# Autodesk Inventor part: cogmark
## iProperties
Author: Neil
Shininess: 42.0
Angle Display Precision: 2
Document Length Units: 11272
Document Angle Units: 11286
Document Time Units: 11279
Document Mass Units: 11290
Document Length Units Precision: 3
Document Angle Units Precision: 2
Compacted: True
PropertySet Name: _Private Model Information
Created: 2001-09
Part Number: cogmark
Material: CogMark
Document SubType Name: Modeling
Designer: Neil
Control State: 0
Master: False
Checked Out: False
PropertySet Name: Design Tracking Control
Density: 0.0
Volumn: 409.0162716240454
Area: 390.0884169359465
PropertySet Name: Model Information
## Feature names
1. Revolution1
2. Extrusion1
3. Circular Pattern1
4. Circular Pattern2
5. Chamfer1
